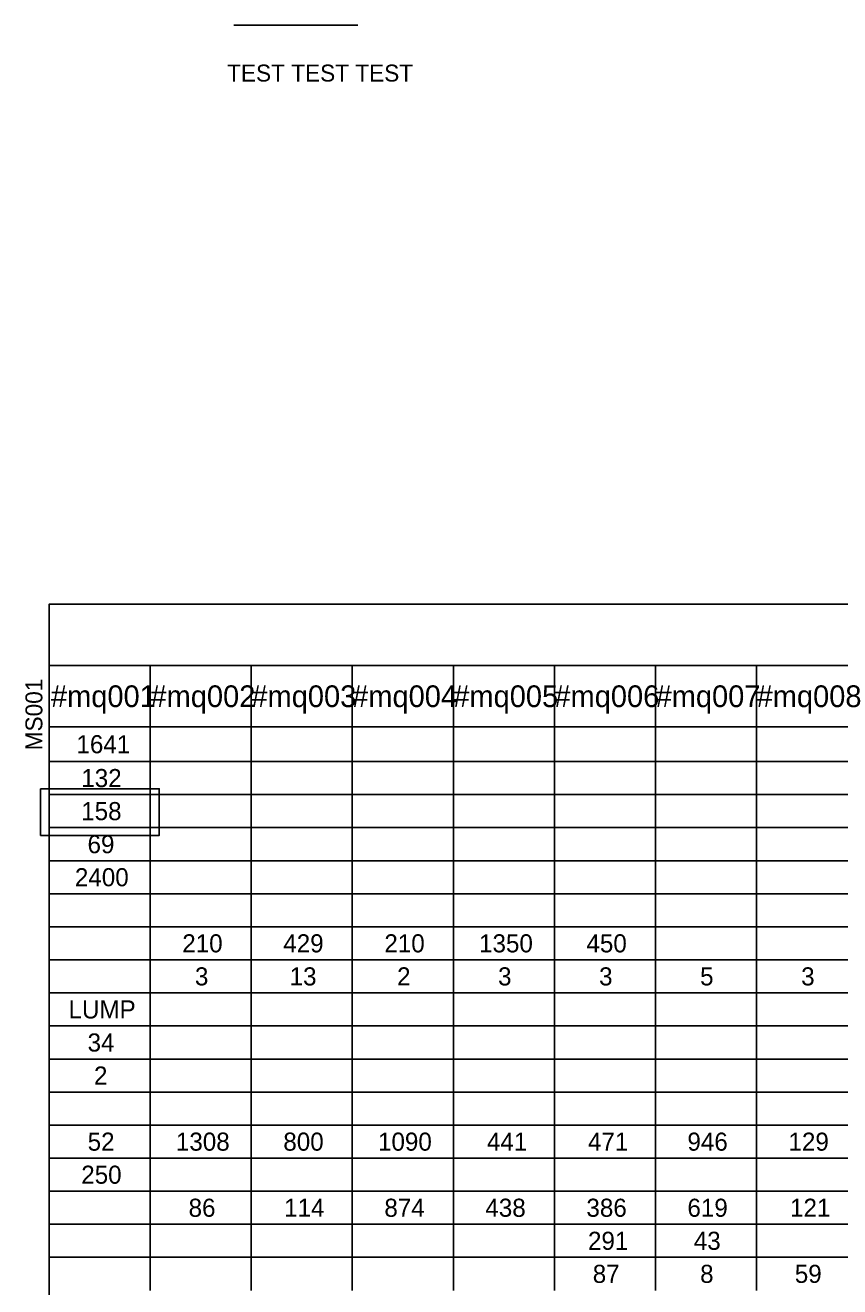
# Model space of a CAD drawing. Extents: x 91011267 to 91012802, y 37012737 to 37014266.
# Drawn here: x 91011267 to 91011605, y 37013505 to 37014027 of the extents above; entities that cross this region are included whole.
import ezdxf

# ---------------------------------------------------------------- set-up
doc = ezdxf.new("R2010")
doc.units = 0
for name, color, linetype in [('AP_P_Airside', 7, 'Continuous'), ('SC_Scratch2', 7, 'Continuous'), ('SH_Data', 7, 'Continuous'), ('SH_Text', 7, 'Continuous')]:
    doc.layers.add(name, color=color, linetype=linetype)

msp = doc.modelspace()

# ---------------------------------------------------------------- linework, layer by layer
at = {"layer": 'AP_P_Airside'}
msp.add_lwpolyline([(91011273.81, 37013710.74), (91011322.89, 37013710.74), (91011322.89, 37013691.45), (91011273.81, 37013691.45)], close=True, dxfattribs=at)
at = {"layer": 'SC_Scratch2'}
msp.add_lwpolyline([(91011277.35, 37013787.1), (91012802.35, 37013787.1), (91012802.35, 37012737.1), (91011277.35, 37012737.1)], close=True, dxfattribs=at)
at = {"layer": 'SH_Data'}
for p, q in [((91011353.71, 37014026.53), (91011405.03, 37014026.53)), ((91011277.35, 37013787.1), (91011653.7, 37013787.1)), ((91011277.35, 37013787.1), (91011277.35, 37013708.33)), ((91011277.35, 37013761.71), (91011653.7, 37013761.71)), ((91011319.17, 37013761.71), (91011319.17, 37013708.33)), ((91011360.98, 37013761.71), (91011360.98, 37013708.33)), ((91011402.8, 37013761.71), (91011402.8, 37013708.33)), ((91011444.62, 37013761.71), (91011444.62, 37013708.33)), ((91011486.43, 37013761.71), (91011486.43, 37013708.33)), ((91011528.25, 37013761.71), (91011528.25, 37013708.33)), ((91011570.07, 37013761.71), (91011570.07, 37013708.33)), ((91011277.35, 37013736.32), (91011653.7, 37013736.32)), ((91011277.35, 37013722), (91011653.7, 37013722)), ((91011277.35, 37013708.33), (91011653.7, 37013708.33)), ((91011277.35, 37013708.33), (91011277.35, 37013694.66)), ((91011319.17, 37013708.33), (91011319.17, 37013694.66)), ((91011360.98, 37013708.33), (91011360.98, 37013694.66)), ((91011402.8, 37013708.33), (91011402.8, 37013694.66)), ((91011444.62, 37013708.33), (91011444.62, 37013694.66)), ((91011486.43, 37013708.33), (91011486.43, 37013694.66)), ((91011528.25, 37013708.33), (91011528.25, 37013694.66)), ((91011570.07, 37013708.33), (91011570.07, 37013694.66)), ((91011277.35, 37013694.66), (91011653.7, 37013694.66)), ((91011277.35, 37013694.66), (91011277.35, 37013626.31)), ((91011319.17, 37013694.66), (91011319.17, 37013626.31)), ((91011360.98, 37013694.66), (91011360.98, 37013626.31)), ((91011402.8, 37013694.66), (91011402.8, 37013626.31)), ((91011444.62, 37013694.66), (91011444.62, 37013626.31)), ((91011486.43, 37013694.66), (91011486.43, 37013626.31)), ((91011528.25, 37013694.66), (91011528.25, 37013626.31)), ((91011570.07, 37013694.66), (91011570.07, 37013626.31)), ((91011277.35, 37013680.99), (91011653.7, 37013680.99)), ((91011277.35, 37013667.32), (91011653.7, 37013667.32)), ((91011277.35, 37013653.65), (91011653.7, 37013653.65)), ((91011277.35, 37013639.98), (91011653.7, 37013639.98)), ((91011277.35, 37013626.31), (91011653.7, 37013626.31)), ((91011277.35, 37013626.31), (91011277.35, 37013612.64)), ((91011319.17, 37013626.31), (91011319.17, 37013612.64)), ((91011360.98, 37013626.31), (91011360.98, 37013612.64)), ((91011402.8, 37013626.31), (91011402.8, 37013612.64)), ((91011444.62, 37013626.31), (91011444.62, 37013612.64)), ((91011486.43, 37013626.31), (91011486.43, 37013612.64)), ((91011528.25, 37013626.31), (91011528.25, 37013612.64)), ((91011570.07, 37013626.31), (91011570.07, 37013612.64)), ((91011277.35, 37013612.64), (91011653.7, 37013612.64)), ((91011277.35, 37013612.64), (91011277.35, 37013598.97)), ((91011319.17, 37013612.64), (91011319.17, 37013598.97)), ((91011360.98, 37013612.64), (91011360.98, 37013598.97)), ((91011402.8, 37013612.64), (91011402.8, 37013598.97)), ((91011444.62, 37013612.64), (91011444.62, 37013598.97)), ((91011486.43, 37013612.64), (91011486.43, 37013598.97)), ((91011528.25, 37013612.64), (91011528.25, 37013598.97)), ((91011570.07, 37013612.64), (91011570.07, 37013598.97)), ((91011277.35, 37013598.97), (91011653.7, 37013598.97)), ((91011277.35, 37013598.97), (91011277.35, 37013503.28)), ((91011319.17, 37013598.97), (91011319.17, 37013503.28)), ((91011360.98, 37013598.97), (91011360.98, 37013503.28)), ((91011402.8, 37013598.97), (91011402.8, 37013503.28)), ((91011444.62, 37013598.97), (91011444.62, 37013503.28)), ((91011486.43, 37013598.97), (91011486.43, 37013503.28)), ((91011528.25, 37013598.97), (91011528.25, 37013503.28)), ((91011570.07, 37013598.97), (91011570.07, 37013503.28)), ((91011277.35, 37013585.3), (91011653.7, 37013585.3)), ((91011277.35, 37013571.63), (91011653.7, 37013571.63)), ((91011277.35, 37013557.96), (91011653.7, 37013557.96)), ((91011277.35, 37013544.29), (91011653.7, 37013544.29)), ((91011277.35, 37013530.62), (91011653.7, 37013530.62)), ((91011277.35, 37013516.95), (91011653.7, 37013516.95))]:
    msp.add_line(p, q, dxfattribs=at)
for points in [[(91011277.35, 37013787.1), (91011277.35, 37013787.1), (91011277.35, 37013761.71), (91011277.35, 37013761.71)], [(91011277.35, 37013787.1), (91011277.35, 37013787.1), (91011277.35, 37013761.71), (91011277.35, 37013761.71)], [(91011277.35, 37013787.1), (91011277.35, 37013787.1), (91011277.35, 37013772.77), (91011277.35, 37013772.77)], [(91011277.35, 37013787.1), (91011277.35, 37013787.1), (91011277.35, 37013772.77), (91011277.35, 37013772.77)], [(91011277.35, 37013787.1), (91011277.35, 37013787.1), (91011277.35, 37013773.43), (91011277.35, 37013773.43)], [(91011277.35, 37013787.1), (91011277.35, 37013787.1), (91011277.35, 37013773.43), (91011277.35, 37013773.43)], [(91011277.35, 37013787.1), (91011277.35, 37013787.1), (91011277.35, 37013773.43), (91011277.35, 37013773.43)], [(91011277.35, 37013787.1), (91011277.35, 37013787.1), (91011277.35, 37013773.43), (91011277.35, 37013773.43)], [(91011277.35, 37013787.1), (91011277.35, 37013787.1), (91011277.35, 37013773.43), (91011277.35, 37013773.43)], [(91011277.35, 37013787.1), (91011277.35, 37013787.1), (91011277.35, 37013773.43), (91011277.35, 37013773.43)], [(91011277.35, 37013787.1), (91011277.35, 37013787.1), (91011277.35, 37013773.43), (91011277.35, 37013773.43)], [(91011277.35, 37013787.1), (91011277.35, 37013787.1), (91011277.35, 37013773.43), (91011277.35, 37013773.43)], [(91011277.35, 37013787.1), (91011277.35, 37013787.1), (91011277.35, 37013773.43), (91011277.35, 37013773.43)], [(91011277.35, 37013787.1), (91011277.35, 37013787.1), (91011277.35, 37013773.43), (91011277.35, 37013773.43)], [(91011277.35, 37013787.1), (91011277.35, 37013787.1), (91011277.35, 37013773.43), (91011277.35, 37013773.43)], [(91011277.35, 37013787.1), (91011277.35, 37013787.1), (91011277.35, 37013773.43), (91011277.35, 37013773.43)], [(91011277.35, 37013787.1), (91011277.35, 37013787.1), (91011277.35, 37013773.43), (91011277.35, 37013773.43)], [(91011277.35, 37013787.1), (91011277.35, 37013787.1), (91011277.35, 37013773.43), (91011277.35, 37013773.43)], [(91011277.35, 37013787.1), (91011277.35, 37013787.1), (91011277.35, 37013773.43), (91011277.35, 37013773.43)], [(91011277.35, 37013787.1), (91011277.35, 37013787.1), (91011277.35, 37013773.43), (91011277.35, 37013773.43)], [(91011277.35, 37013787.1), (91011277.35, 37013787.1), (91011277.35, 37013773.43), (91011277.35, 37013773.43)], [(91011277.35, 37013787.1), (91011277.35, 37013787.1), (91011277.35, 37013773.43), (91011277.35, 37013773.43)], [(91011277.35, 37013787.1), (91011277.35, 37013787.1), (91011277.35, 37013773.43), (91011277.35, 37013773.43)], [(91011277.35, 37013787.1), (91011277.35, 37013787.1), (91011277.35, 37013773.43), (91011277.35, 37013773.43)], [(91011277.35, 37013787.1), (91011277.35, 37013787.1), (91011277.35, 37013773.43), (91011277.35, 37013773.43)], [(91011277.35, 37013787.1), (91011277.35, 37013787.1), (91011277.35, 37013773.43), (91011277.35, 37013773.43)], [(91011277.35, 37013787.1), (91011277.35, 37013787.1), (91011277.35, 37013773.43), (91011277.35, 37013773.43)], [(91011277.35, 37013787.1), (91011277.35, 37013787.1), (91011277.35, 37013773.43), (91011277.35, 37013773.43)], [(91011277.35, 37013787.1), (91011277.35, 37013787.1), (91011277.35, 37013773.43), (91011277.35, 37013773.43)], [(91011277.35, 37013787.1), (91011277.35, 37013787.1), (91011277.35, 37013773.43), (91011277.35, 37013773.43)], [(91011277.35, 37013787.1), (91011277.35, 37013787.1), (91011277.35, 37013773.43), (91011277.35, 37013773.43)], [(91011277.35, 37013787.1), (91011277.35, 37013787.1), (91011277.35, 37013773.43), (91011277.35, 37013773.43)], [(91011277.35, 37013787.1), (91011277.35, 37013787.1), (91011277.35, 37013773.43), (91011277.35, 37013773.43)], [(91011277.35, 37013787.1), (91011277.35, 37013787.1), (91011277.35, 37013773.43), (91011277.35, 37013773.43)], [(91011277.35, 37013787.1), (91011277.35, 37013787.1), (91011277.35, 37013773.43), (91011277.35, 37013773.43)], [(91011277.35, 37013787.1), (91011277.35, 37013787.1), (91011277.35, 37013773.43), (91011277.35, 37013773.43)], [(91011277.35, 37013787.1), (91011277.35, 37013787.1), (91011277.35, 37013773.43), (91011277.35, 37013773.43)], [(91011277.35, 37013787.1), (91011277.35, 37013787.1), (91011277.35, 37013773.43), (91011277.35, 37013773.43)], [(91011277.35, 37013787.1), (91011277.35, 37013787.1), (91011277.35, 37013773.43), (91011277.35, 37013773.43)], [(91011277.35, 37013787.1), (91011277.35, 37013787.1), (91011277.35, 37013773.43), (91011277.35, 37013773.43)], [(91011277.35, 37013787.1), (91011277.35, 37013787.1), (91011277.35, 37013773.43), (91011277.35, 37013773.43)], [(91011277.35, 37013787.1), (91011277.35, 37013787.1), (91011277.35, 37013773.43), (91011277.35, 37013773.43)], [(91011277.35, 37013787.1), (91011277.35, 37013787.1), (91011277.35, 37013773.43), (91011277.35, 37013773.43)], [(91011277.35, 37013787.1), (91011277.35, 37013787.1), (91011277.35, 37013773.43), (91011277.35, 37013773.43)], [(91011277.35, 37013787.1), (91011277.35, 37013787.1), (91011277.35, 37013773.43), (91011277.35, 37013773.43)], [(91011277.35, 37013787.1), (91011277.35, 37013787.1), (91011277.35, 37013773.43), (91011277.35, 37013773.43)], [(91011277.35, 37013787.1), (91011277.35, 37013787.1), (91011277.35, 37013773.43), (91011277.35, 37013773.43)], [(91011277.35, 37013787.1), (91011277.35, 37013787.1), (91011277.35, 37013773.43), (91011277.35, 37013773.43)], [(91011277.35, 37013787.1), (91011277.35, 37013787.1), (91011277.35, 37013773.43), (91011277.35, 37013773.43)], [(91011277.35, 37013787.1), (91011277.35, 37013787.1), (91011277.35, 37013773.43), (91011277.35, 37013773.43)], [(91011277.35, 37013787.1), (91011277.35, 37013787.1), (91011277.35, 37013773.43), (91011277.35, 37013773.43)], [(91011277.35, 37013787.1), (91011277.35, 37013787.1), (91011277.35, 37013773.43), (91011277.35, 37013773.43)], [(91011277.35, 37013787.1), (91011277.35, 37013787.1), (91011277.35, 37013773.43), (91011277.35, 37013773.43)], [(91011277.35, 37013787.1), (91011277.35, 37013787.1), (91011277.35, 37013773.43), (91011277.35, 37013773.43)], [(91011277.35, 37013787.1), (91011277.35, 37013787.1), (91011277.35, 37013773.43), (91011277.35, 37013773.43)], [(91011277.35, 37013787.1), (91011277.35, 37013787.1), (91011277.35, 37013773.43), (91011277.35, 37013773.43)], [(91011277.35, 37013787.1), (91011277.35, 37013787.1), (91011277.35, 37013773.43), (91011277.35, 37013773.43)], [(91011277.35, 37013787.1), (91011277.35, 37013787.1), (91011277.35, 37013773.43), (91011277.35, 37013773.43)], [(91011277.35, 37013787.1), (91011277.35, 37013787.1), (91011277.35, 37013773.43), (91011277.35, 37013773.43)], [(91011277.35, 37013787.1), (91011277.35, 37013787.1), (91011277.35, 37013773.43), (91011277.35, 37013773.43)], [(91011277.35, 37013787.1), (91011277.35, 37013787.1), (91011277.35, 37013773.43), (91011277.35, 37013773.43)], [(91011277.35, 37013787.1), (91011277.35, 37013787.1), (91011277.35, 37013773.43), (91011277.35, 37013773.43)], [(91011277.35, 37013787.1), (91011277.35, 37013787.1), (91011277.35, 37013773.43), (91011277.35, 37013773.43)], [(91011277.35, 37013787.1), (91011277.35, 37013787.1), (91011277.35, 37013773.43), (91011277.35, 37013773.43)], [(91011277.35, 37013787.1), (91011277.35, 37013787.1), (91011277.35, 37013773.43), (91011277.35, 37013773.43)], [(91011277.35, 37013787.1), (91011277.35, 37013787.1), (91011277.35, 37013773.43), (91011277.35, 37013773.43)], [(91011277.35, 37013787.1), (91011277.35, 37013787.1), (91011277.35, 37013773.43), (91011277.35, 37013773.43)], [(91011277.35, 37013787.1), (91011277.35, 37013787.1), (91011277.35, 37013773.43), (91011277.35, 37013773.43)], [(91011277.35, 37013787.1), (91011277.35, 37013787.1), (91011277.35, 37013773.43), (91011277.35, 37013773.43)], [(91011277.35, 37013787.1), (91011277.35, 37013787.1), (91011277.35, 37013773.43), (91011277.35, 37013773.43)], [(91011277.35, 37013787.1), (91011277.35, 37013787.1), (91011277.35, 37013773.43), (91011277.35, 37013773.43)], [(91011277.35, 37013787.1), (91011277.35, 37013787.1), (91011277.35, 37013773.43), (91011277.35, 37013773.43)], [(91011277.35, 37013787.1), (91011277.35, 37013787.1), (91011277.35, 37013773.43), (91011277.35, 37013773.43)], [(91011277.35, 37013787.1), (91011277.35, 37013787.1), (91011277.35, 37013773.43), (91011277.35, 37013773.43)], [(91011277.35, 37013787.1), (91011277.35, 37013787.1), (91011277.35, 37013773.43), (91011277.35, 37013773.43)], [(91011277.35, 37013787.1), (91011277.35, 37013787.1), (91011277.35, 37013773.43), (91011277.35, 37013773.43)], [(91011277.35, 37013787.1), (91011277.35, 37013787.1), (91011277.35, 37013773.43), (91011277.35, 37013773.43)], [(91011277.35, 37013787.1), (91011277.35, 37013787.1), (91011277.35, 37013773.43), (91011277.35, 37013773.43)], [(91011277.35, 37013787.1), (91011277.35, 37013787.1), (91011277.35, 37013773.43), (91011277.35, 37013773.43)], [(91011277.35, 37013787.1), (91011277.35, 37013787.1), (91011277.35, 37013773.43), (91011277.35, 37013773.43)], [(91011277.35, 37013787.1), (91011277.35, 37013787.1), (91011277.35, 37013773.43), (91011277.35, 37013773.43)], [(91011277.35, 37013787.1), (91011277.35, 37013787.1), (91011277.35, 37013773.43), (91011277.35, 37013773.43)], [(91011277.35, 37013787.1), (91011277.35, 37013787.1), (91011277.35, 37013773.43), (91011277.35, 37013773.43)], [(91011277.35, 37013787.1), (91011277.35, 37013787.1), (91011277.35, 37013773.43), (91011277.35, 37013773.43)], [(91011277.35, 37013787.1), (91011277.35, 37013787.1), (91011277.35, 37013773.43), (91011277.35, 37013773.43)], [(91011277.35, 37013787.1), (91011277.35, 37013787.1), (91011277.35, 37013773.43), (91011277.35, 37013773.43)], [(91011277.35, 37013787.1), (91011277.35, 37013787.1), (91011277.35, 37013773.43), (91011277.35, 37013773.43)], [(91011277.35, 37013787.1), (91011277.35, 37013787.1), (91011277.35, 37013773.43), (91011277.35, 37013773.43)], [(91011277.35, 37013787.1), (91011277.35, 37013787.1), (91011277.35, 37013773.43), (91011277.35, 37013773.43)], [(91011277.35, 37013787.1), (91011277.35, 37013787.1), (91011277.35, 37013773.43), (91011277.35, 37013773.43)], [(91011277.35, 37013787.1), (91011277.35, 37013787.1), (91011277.35, 37013773.43), (91011277.35, 37013773.43)], [(91011277.35, 37013787.1), (91011277.35, 37013787.1), (91011277.35, 37013773.43), (91011277.35, 37013773.43)], [(91011277.35, 37013787.1), (91011277.35, 37013787.1), (91011277.35, 37013773.43), (91011277.35, 37013773.43)], [(91011277.35, 37013787.1), (91011277.35, 37013787.1), (91011277.35, 37013773.43), (91011277.35, 37013773.43)], [(91011277.35, 37013787.1), (91011277.35, 37013787.1), (91011277.35, 37013773.43), (91011277.35, 37013773.43)], [(91011277.35, 37013787.1), (91011277.35, 37013787.1), (91011277.35, 37013773.43), (91011277.35, 37013773.43)], [(91011277.35, 37013787.1), (91011277.35, 37013787.1), (91011277.35, 37013773.43), (91011277.35, 37013773.43)], [(91011277.35, 37013787.1), (91011277.35, 37013787.1), (91011277.35, 37013773.43), (91011277.35, 37013773.43)], [(91011277.35, 37013787.1), (91011277.35, 37013787.1), (91011277.35, 37013773.43), (91011277.35, 37013773.43)], [(91011277.35, 37013787.1), (91011277.35, 37013787.1), (91011277.35, 37013773.43), (91011277.35, 37013773.43)], [(91011277.35, 37013787.1), (91011277.35, 37013787.1), (91011277.35, 37013773.43), (91011277.35, 37013773.43)], [(91011277.35, 37013787.1), (91011277.35, 37013787.1), (91011277.35, 37013773.43), (91011277.35, 37013773.43)], [(91011277.35, 37013787.1), (91011277.35, 37013787.1), (91011277.35, 37013773.43), (91011277.35, 37013773.43)], [(91011277.35, 37013787.1), (91011277.35, 37013787.1), (91011277.35, 37013773.43), (91011277.35, 37013773.43)], [(91011277.35, 37013787.1), (91011277.35, 37013787.1), (91011277.35, 37013773.43), (91011277.35, 37013773.43)], [(91011277.35, 37013787.1), (91011277.35, 37013787.1), (91011277.35, 37013773.43), (91011277.35, 37013773.43)], [(91011277.35, 37013787.1), (91011277.35, 37013787.1), (91011277.35, 37013773.43), (91011277.35, 37013773.43)], [(91011277.35, 37013787.1), (91011277.35, 37013787.1), (91011277.35, 37013773.43), (91011277.35, 37013773.43)], [(91011277.35, 37013787.1), (91011277.35, 37013787.1), (91011277.35, 37013773.43), (91011277.35, 37013773.43)], [(91011277.35, 37013787.1), (91011277.35, 37013787.1), (91011277.35, 37013773.43), (91011277.35, 37013773.43)], [(91011277.35, 37013787.1), (91011277.35, 37013787.1), (91011277.35, 37013773.43), (91011277.35, 37013773.43)], [(91011277.35, 37013787.1), (91011277.35, 37013787.1), (91011277.35, 37013773.43), (91011277.35, 37013773.43)], [(91011277.35, 37013787.1), (91011277.35, 37013787.1), (91011277.35, 37013773.43), (91011277.35, 37013773.43)], [(91011277.35, 37013787.1), (91011277.35, 37013787.1), (91011277.35, 37013773.43), (91011277.35, 37013773.43)], [(91011277.35, 37013787.1), (91011277.35, 37013787.1), (91011277.35, 37013773.43), (91011277.35, 37013773.43)], [(91011277.35, 37013787.1), (91011277.35, 37013787.1), (91011277.35, 37013773.43), (91011277.35, 37013773.43)], [(91011277.35, 37013787.1), (91011277.35, 37013787.1), (91011277.35, 37013773.43), (91011277.35, 37013773.43)], [(91011277.35, 37013787.1), (91011277.35, 37013787.1), (91011277.35, 37013773.43), (91011277.35, 37013773.43)], [(91011277.35, 37013787.1), (91011277.35, 37013787.1), (91011277.35, 37013773.43), (91011277.35, 37013773.43)], [(91011277.35, 37013787.1), (91011277.35, 37013787.1), (91011277.35, 37013773.43), (91011277.35, 37013773.43)], [(91011277.35, 37013787.1), (91011277.35, 37013787.1), (91011277.35, 37013773.43), (91011277.35, 37013773.43)], [(91011277.35, 37013787.1), (91011277.35, 37013787.1), (91011277.35, 37013773.43), (91011277.35, 37013773.43)], [(91011277.35, 37013787.1), (91011277.35, 37013787.1), (91011277.35, 37013773.43), (91011277.35, 37013773.43)], [(91011277.35, 37013787.1), (91011277.35, 37013787.1), (91011277.35, 37013773.43), (91011277.35, 37013773.43)], [(91011277.35, 37013787.1), (91011277.35, 37013787.1), (91011277.35, 37013773.43), (91011277.35, 37013773.43)], [(91011277.35, 37013787.1), (91011277.35, 37013787.1), (91011277.35, 37013773.43), (91011277.35, 37013773.43)], [(91011277.35, 37013787.1), (91011277.35, 37013787.1), (91011277.35, 37013773.43), (91011277.35, 37013773.43)], [(91011277.35, 37013787.1), (91011277.35, 37013787.1), (91011277.35, 37013773.43), (91011277.35, 37013773.43)], [(91011277.35, 37013787.1), (91011277.35, 37013787.1), (91011277.35, 37013773.43), (91011277.35, 37013773.43)], [(91011277.35, 37013787.1), (91011277.35, 37013787.1), (91011277.35, 37013773.43), (91011277.35, 37013773.43)], [(91011277.35, 37013787.1), (91011277.35, 37013787.1), (91011277.35, 37013773.43), (91011277.35, 37013773.43)], [(91011277.35, 37013787.1), (91011277.35, 37013787.1), (91011277.35, 37013773.43), (91011277.35, 37013773.43)], [(91011277.35, 37013787.1), (91011277.35, 37013787.1), (91011277.35, 37013773.43), (91011277.35, 37013773.43)], [(91011277.35, 37013787.1), (91011277.35, 37013787.1), (91011277.35, 37013773.43), (91011277.35, 37013773.43)], [(91011277.35, 37013787.1), (91011277.35, 37013787.1), (91011277.35, 37013773.43), (91011277.35, 37013773.43)], [(91011277.35, 37013787.1), (91011277.35, 37013787.1), (91011277.35, 37013773.43), (91011277.35, 37013773.43)], [(91011277.35, 37013787.1), (91011277.35, 37013787.1), (91011277.35, 37013773.43), (91011277.35, 37013773.43)], [(91011277.35, 37013787.1), (91011277.35, 37013787.1), (91011277.35, 37013773.43), (91011277.35, 37013773.43)], [(91011277.35, 37013787.1), (91011277.35, 37013787.1), (91011277.35, 37013773.43), (91011277.35, 37013773.43)], [(91011277.35, 37013787.1), (91011277.35, 37013787.1), (91011277.35, 37013773.43), (91011277.35, 37013773.43)], [(91011277.35, 37013787.1), (91011277.35, 37013787.1), (91011277.35, 37013773.43), (91011277.35, 37013773.43)], [(91011277.35, 37013787.1), (91011277.35, 37013787.1), (91011277.35, 37013773.43), (91011277.35, 37013773.43)], [(91011277.35, 37013787.1), (91011277.35, 37013787.1), (91011277.35, 37013773.43), (91011277.35, 37013773.43)], [(91011277.35, 37013787.1), (91011277.35, 37013787.1), (91011277.35, 37013773.43), (91011277.35, 37013773.43)], [(91011277.35, 37013787.1), (91011277.35, 37013787.1), (91011277.35, 37013773.43), (91011277.35, 37013773.43)], [(91011277.35, 37013787.1), (91011277.35, 37013787.1), (91011277.35, 37013773.43), (91011277.35, 37013773.43)], [(91011277.35, 37013787.1), (91011277.35, 37013787.1), (91011277.35, 37013772.77), (91011277.35, 37013772.77)], [(91011277.35, 37013787.1), (91011277.35, 37013787.1), (91011277.35, 37013772.77), (91011277.35, 37013772.77)]]:
    msp.add_lwpolyline(points, close=True, dxfattribs=at)

# ---------------------------------------------------------------- texts
for s, height, p in [('TEST TEST TEST', 7, (91011350.99, 37014003.25)), ('#mq001', 8.983, (91011278.07, 37013744.52)), ('#mq002', 8.983, (91011319.25, 37013744.52)), ('#mq003', 8.983, (91011361.03, 37013744.52)), ('#mq004', 8.983, (91011402.73, 37013744.52)), ('#mq005', 8.983, (91011444.58, 37013744.52)), ('#mq006', 8.983, (91011486.43, 37013744.52)), ('#mq007', 8.983, (91011528.3, 37013744.52)), ('#mq008', 8.983, (91011570.12, 37013744.52)), ('1641', 7.486, (91011288.62, 37013725.42)), ('132', 7.486, (91011290.63, 37013711.42)), ('158', 7.486, (91011290.59, 37013697.75)), ('69', 7.486, (91011293.21, 37013684.08)), ('2400', 7.486, (91011287.98, 37013670.41)), ('210', 7.486, (91011332.42, 37013643.07)), ('429', 7.486, (91011374.22, 37013643.07)), ('210', 7.486, (91011416.06, 37013643.07)), ('1350', 7.486, (91011455.25, 37013643.07)), ('450', 7.486, (91011499.69, 37013643.07)), ('3', 7.49, (91011337.66, 37013629.4)), ('13', 7.486, (91011376.85, 37013629.4)), ('2', 7.49, (91011421.33, 37013629.4)), ('3', 7.49, (91011463.11, 37013629.4)), ('3', 7.49, (91011504.93, 37013629.4)), ('5', 7.49, (91011546.72, 37013629.4)), ('3', 7.49, (91011588.56, 37013629.4)), ('LUMP', 7.486, (91011285.34, 37013615.73)), ('34', 7.486, (91011293.24, 37013602.06)), ('2', 7.49, (91011295.88, 37013588.39)), ('52', 7.486, (91011293.26, 37013561.05)), ('1308', 7.486, (91011329.78, 37013561.05)), ('800', 7.486, (91011374.24, 37013561.05)), ('1090', 7.486, (91011413.43, 37013561.05)), ('441', 7.486, (91011458.52, 37013561.05)), ('471', 7.486, (91011500.33, 37013561.05)), ('946', 7.486, (91011541.49, 37013561.05)), ('129', 7.486, (91011583.31, 37013561.05)), ('250', 7.486, (91011290.61, 37013547.38)), ('86', 7.486, (91011335.04, 37013533.71)), ('114', 7.486, (91011374.59, 37013533.71)), ('874', 7.486, (91011416.06, 37013533.71)), ('438', 7.486, (91011457.86, 37013533.71)), ('386', 7.486, (91011499.68, 37013533.71)), ('619', 7.486, (91011541.49, 37013533.71)), ('121', 7.486, (91011583.96, 37013533.71)), ('291', 7.486, (91011500.33, 37013520.04)), ('43', 7.486, (91011544.12, 37013520.04)), ('87', 7.486, (91011502.3, 37013506.37)), ('8', 7.49, (91011546.74, 37013506.37)), ('59', 7.486, (91011585.93, 37013506.37))]:
    msp.add_text(s, height=height, dxfattribs=at).set_placement(p)
at = {"layer": 'SH_Text'}
msp.add_text('MS001', height=7, rotation=90, dxfattribs=at).set_placement((91011274.52, 37013726.63))

doc.saveas('drawing.dxf')
